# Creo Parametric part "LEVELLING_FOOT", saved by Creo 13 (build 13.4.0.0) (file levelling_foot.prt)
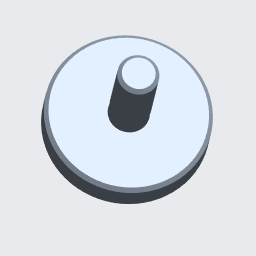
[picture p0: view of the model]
Units: millimeter Newton Second (mmNs); MM, TONNE, SECS

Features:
  1. datum plane "RIGHT"
  2. datum plane "TOP"
  3. datum plane "FRONT"
  4. coordinate system
  5. protrusion
  6. protrusion
  7. chamfer

Surfaces: 4 cone, 3 plane, 2 cylinder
